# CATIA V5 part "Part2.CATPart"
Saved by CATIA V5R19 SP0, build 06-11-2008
Part number: Up_pouch
Bounding box of the stored display mesh (mm): x -1 to 42.5, y -8 to 17, z 70 to 83
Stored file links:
  C:\Users\sisca\Desktop\HELTEC_CASE\Part2.CATPart
  C:\Users\sisca\Desktop\HELTEC_CASE\Custodia pouch.CATPart
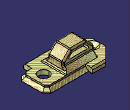
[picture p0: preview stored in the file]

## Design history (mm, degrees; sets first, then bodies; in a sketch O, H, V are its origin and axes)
Set1
  DatumCurve1 to DatumCurve4
  DatumSurface1
  CLDGeom1 "Tessellation.1"
Body1 (main body)
  Sketch1, origin (0, 0, 70), H (1, 0, 0), V (0, 1, 0)
    line L1 (15.5, 14.5) -> (39.7929, 14.5)
    line L2 (39.7929, 14.5) -> (42.5, 11.7929)
    line L3 (42.5, -1.7929) -> (42.5, 11.7929)
    line L4 (42.5, -1.7929) -> (39.7929, -4.5)
    line L5 (39.7929, -4.5) -> (35, -4.5)
    line L6 (35, -8) -> (35, -4.5)
    line L7 (15.5, 14.5) -> (15.5, 17)
    line L8 (15.5, 17) -> (7, 17)
    line L9 (7, -8) -> (35, -8)
    line L10 (-1, 9) -> (-1, 0)
    line L11 (-1, 9) -> (7, 17)
    line L12 (7, -8) -> (-1, 0)
    distance L9 L8 = 25
    vertical: L6 V, L7 V
  Pad1: profile Sketch1, direction (0, 0, 1), length 2
  Chamfer1: length 2, angle 45, on edge [face of Pad1 from Sketch1.L1 | end face of Pad1]; edge [face of Pad1 from Sketch1.L2 | end face of Pad1]; edge [face of Pad1 from Sketch1.L3 | end face of Pad1]; edge [face of Pad1 from Sketch1.L4 | end face of Pad1]; edge [face of Pad1 from Sketch1.L5 | end face of Pad1]
  Sketch2 on end face of Pad1, origin (0, 0, 72), H (1, 0, 0), V (0, 1, 0)
  Pad2: profile Sketch2, direction (0, 0, 1), length 1
  Chamfer2: length 1, angle 45, on edge [face of Pad2 | end face of Pad2] (x2)
  Sketch3 on end face of Pad2, origin (0, 0, 73), H (1, 0, 0), V (0, 1, 0)
    line L1 (7, 9.5) -> (27, 9.5)
    line L2 (27, 9.5) -> (27, -0.5)
    line L3 (27, -0.5) -> (7, -0.5)
    line L4 (7, -0.5) -> (7, 9.5)
    construction line L5 (7, 13.1716) -> (7, -4.1716)
    length L2 = 10
    distance L2 L4 = 20
    distance L4 L5 = 0
    horizontal: L1 H, L3 H
    vertical: L2 V, L4 V
  Pad3: profile Sketch3, direction (0, 0, 1), length 10
  Chamfer3: length 3, angle 45, on edge [end face of Pad2 | face of Pad3 from Sketch3.L3]; edge [end face of Pad2 | face of Pad3 from Sketch3.L1]
  Chamfer4: length 5, angle 45, on edge [face of Pad3 from Sketch3.L2 | end face of Pad3]
  Chamfer5: length 5, angle 45, on edge [face of Pad3 from Sketch3.L4 | end face of Pad3]
  Sketch4 on face of Pad3 from Sketch3.L1, origin (0, 9.5, 0), H (-1, 0, 0), V (0, 0, 1)
  Pocket1: profile Sketch4, direction (0, -1, 0), length 10
  Fillet1: radius 0.5, on edge [face of Pocket1 | face of Pocket1] (x4)
  Chamfer6: length 1, angle 45, on edge [face of Pad3 from Sketch3.L2 | end face of Pad2]
  Fillet2: radius 1, on edge [face of Pad3 from Sketch3.L3 | face of Chamfer3]; edge [face of Pad3 from Sketch3.L1 | face of Chamfer3]
  Fillet3: radius 1, on edge [face of Pad3 from Sketch3.L1 | end face of Pad3]; edge [face of Pad3 from Sketch3.L3 | end face of Pad3]
  Fillet4: radius 1, on edge [face of Pad3 from Sketch3.L2 | face of Chamfer4]; edge [face of Pad3 from Sketch3.L4 | face of Chamfer5]
  Fillet5: radius 1, on edge [face of Chamfer5 | end face of Pad3]; edge [face of Chamfer4 | end face of Pad3]
  Fillet6: radius 1, on edge [end face of Pad2 | face of Chamfer6]
  Sketch5 on end face of Pad2, origin (0, 0, 73), H (1, 0, 0), V (0, 1, 0)
    circle A1 centre (34.5, 4.5) radius 3.5
    point P1 (34.5, 4.5)
    reference projected line E1 (38.9645, 12.5) -> (22, 12.5) from edge [face of Pad2 | end face of Pad2]
    reference projected line E2 (40.5, -0.9645) -> (40.5, 10.9645) from edge [face of Pad2 | end face of Pad2]
    radius A1 = 3.5
    distance P1 E1 = 8
    distance P1 E2 = 6
  Pocket2: profile Sketch5, direction (0, 0, -1), length 4, opposite side through (limit type 6)
  Sketch6 on end face of Pad2, origin (2.3656, 6.2295, 73), H (1, 0, 0), V (0, 1, 0)
    point P1 (0.6344, -2.2295)
    reference projected circle E1 centre (0.6344, -2.2295) radius 3 from edge of DatumCurve4
    concentricity: E1 P1
  Hole1: placed by Sketch6, at (3, 4, 73) direction (0, 0, -1), diameter 3.5, through (limit type 6), countersink depth 2, countersink angle 90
